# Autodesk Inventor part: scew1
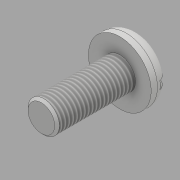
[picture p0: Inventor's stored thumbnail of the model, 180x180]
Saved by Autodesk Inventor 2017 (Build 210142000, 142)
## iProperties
Created: 2016-05
Part Number: scew1
Material: Generic
Document SubType Name: Modeling
Designer: CADCIM
Density: 1 g/cm^3
Appearance: Default
Author: CADCIM
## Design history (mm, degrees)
sketch "Sketch1"
  geometry: C1 r 12 at (0, 0); 1 further point
  constraints: 1 centre point, 1 coincident
  dimensions: "d0" = 24 diameter of C1
extrude "Extrusion1" new body sketch "Sketch1" distance "d1" = 7.2; taper "d2" = 0 deg
fillet "Fillet1" dims "d3" = 4.8
sketch "Sketch2"
  geometry: L1 (-13.413, -1.5)-(14.543, -1.5); L2 (14.543, -1.5)-(14.543, 1.5); L3 (14.543, 1.5)-(-13.413, 1.5); L4 (-13.413, 1.5)-(-13.413, -1.5); L5 (0, 0)-(-14.109, 0)
  constraints: 10 end point, 2 parallel, 2 perpendicular, 1 horizontal, 1 other
  dimensions: "d4" = 3 distance of L1.end L2.end
extrude "Extrusion2" cut sketch "Sketch2" distance "d5" = 3.6; taper "d6" = 0 deg
sketch "Sketch3"
  geometry: C1 r 6 at (0, 0); 1 further point
  constraints: 1 centre point, 1 coincident
  dimensions: "d7" = 12 diameter of C1
extrude "Extrusion3" join sketch "Sketch3" distance "d8" = 30; taper "d9" = 0 deg
thread "Thread1" dims "d13" = 10, "d14" = 0
chamfer "Chamfer2" distance "d15" = 0.9; stored, may be unused: second distance "d16" = 2, angle "d17" = 45 deg
body "Solid1"
